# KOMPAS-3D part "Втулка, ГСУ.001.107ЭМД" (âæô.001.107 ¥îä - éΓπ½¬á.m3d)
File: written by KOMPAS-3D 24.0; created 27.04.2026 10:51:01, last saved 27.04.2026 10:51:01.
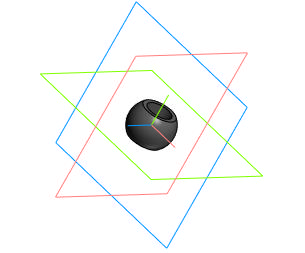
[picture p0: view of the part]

Document properties: Автор: USG_411; Полное имя файла: C:\Users\USG_411\Desktop\ГМ2704_411-15\Двигатель мясорубки\ГСУ.001.107 ЭМД - Втулка.m3d

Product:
- Part/product: Втулка  | designation ГСУ.001.107ЭМД
    Масса: 0.007197

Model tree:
1. Сфера:1
     Диаметр = 14.6
2. Эскиз:1
3. Элемент выдавливания:1
     Расстояние 1 = 50
4. Зеркальный массив:1
5. Экземпляр ( 1 )
6. Экземпляр ( 2 )  (with: Элемент выдавливания:1)
7. Эскиз:2  (with: Грань.Элемент выдавливания:1)
8. Элемент выдавливания:2
     Расстояние 2 = 10

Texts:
  ГСУ.001.107
  ГСУ.001.107 ЭМД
